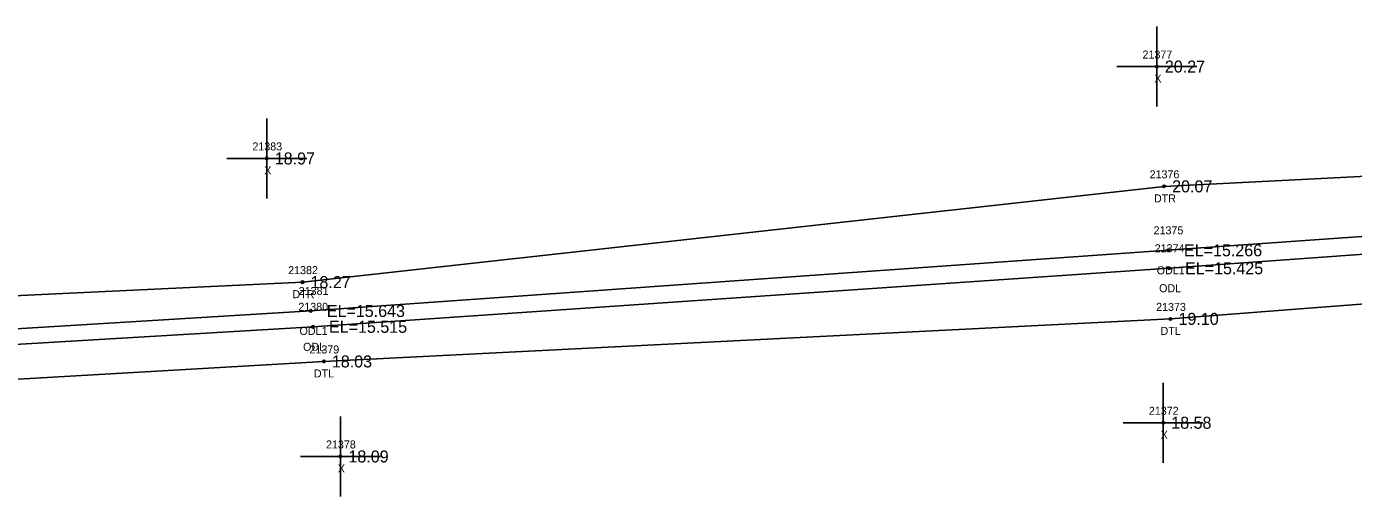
# Model space of a CAD drawing. Extents: x 2655177 to 2656219, y 761780 to 764748.
# Drawn here: x 2655435.9 to 2655601.7, y 763532.7 to 763591.4 of the extents above; entities that cross this region are included whole.
import ezdxf

# ---------------------------------------------------------------- set-up
doc = ezdxf.new("R2010")
doc.units = 0
for name, color, linetype in [('RD_EX_H2O', 7, 'Continuous'), ('RD_EX_H2O_txCode', 7, 'Continuous'), ('RD_EX_Misc', 7, 'Continuous'), ('RD_EX_Misc_txCode', 7, 'Continuous'), ('RD_EX_TX_H2O_ELEV', 7, 'Continuous'), ('RD_EX_TX_Misc_ELEV', 7, 'Continuous'), ('RD_SMD_Locator', 7, 'Continuous')]:
    doc.layers.add(name, color=color, linetype=linetype)

msp = doc.modelspace()

# ---------------------------------------------------------------- linework, layer by layer
at = {"layer": 'RD_EX_H2O'}
for points in [[(2655757.45, 763580.99), (2655680.96, 763576.66), (2655578.06, 763571.44), (2655470.41, 763559.47), (2655370.94, 763554.75), (2655276.75, 763546.33)], [(2655759.35, 763565.01), (2655680.83, 763570.66), (2655578.54, 763563.45), (2655471.45, 763555.87), (2655371.16, 763549.76), (2655277.06, 763543.35)], [(2655759.35, 763565.01), (2655680.78, 763568.55), (2655578.67, 763561.21), (2655471.72, 763553.89), (2655371.24, 763547.95), (2655277.37, 763540.37)], [(2655751.61, 763561.47), (2655681.52, 763562.81), (2655578.85, 763554.88), (2655473.08, 763549.56), (2655371.46, 763543.69), (2655277.89, 763535.39)]]:
    msp.add_lwpolyline(points, dxfattribs=at)
at = {"layer": 'RD_EX_Misc'}
for p, q in [((2655577.15, 763581.41), (2655577.15, 763591.41)), ((2655572.15, 763586.41), (2655582.15, 763586.41)), ((2655465.95, 763569.93), (2655465.95, 763579.93)), ((2655460.95, 763574.93), (2655470.95, 763574.93)), ((2655577.95, 763536.9), (2655577.95, 763546.9)), ((2655475.15, 763532.69), (2655475.15, 763542.69)), ((2655572.95, 763541.9), (2655582.95, 763541.9)), ((2655470.15, 763537.69), (2655480.15, 763537.69))]:
    msp.add_line(p, q, dxfattribs=at)
at = {"layer": 'RD_SMD_Locator'}
for centre in [(2655577.15, 763586.41), (2655465.95, 763574.93), (2655578.06, 763571.44), (2655578.54, 763563.45), (2655578.67, 763561.21), (2655470.41, 763559.47), (2655471.45, 763555.87), (2655578.85, 763554.88), (2655471.72, 763553.89), (2655473.08, 763549.56), (2655577.95, 763541.9), (2655475.15, 763537.69)]:
    msp.add_circle(centre, 0.15, dxfattribs=at)

# ---------------------------------------------------------------- texts
at = {"layer": 'RD_EX_H2O_txCode'}
for s, p in [('21376', (2655576.24, 763572.44)), ('DTR', (2655576.79, 763569.44)), ('21375', (2655576.74, 763565.45)), ('21374', (2655576.88, 763563.21)), ('21382', (2655468.62, 763560.47)), ('ODL1', (2655577.13, 763560.45)), ('ODL', (2655577.43, 763558.21)), ('DTR', (2655469.15, 763557.47)), ('21381', (2655469.94, 763557.87)), ('21380', (2655469.89, 763555.89)), ('21373', (2655577.06, 763555.88)), ('ODL1', (2655470.04, 763552.87)), ('DTL', (2655577.61, 763552.88)), ('ODL', (2655470.48, 763550.89)), ('21379', (2655471.28, 763550.56)), ('DTL', (2655471.83, 763547.56))]:
    msp.add_text(s, height=1, dxfattribs=at).set_placement(p)
at = {"layer": 'RD_EX_Misc_txCode'}
for s, p in [('21377', (2655575.36, 763587.41)), ('X', (2655576.84, 763584.41)), ('21383', (2655464.15, 763575.93)), ('X', (2655465.63, 763572.93)), ('21372', (2655576.15, 763542.9)), ('X', (2655577.63, 763539.9)), ('21378', (2655473.35, 763538.69)), ('X', (2655474.83, 763535.69))]:
    msp.add_text(s, height=1, dxfattribs=at).set_placement(p)
at = {"layer": 'RD_EX_TX_H2O_ELEV'}
for s, p in [('20.07', (2655579.06, 763570.69)), ('EL=15.266', (2655580.54, 763562.7)), ('EL=15.425', (2655580.67, 763560.46)), ('18.27', (2655471.41, 763558.72)), ('EL=15.643', (2655473.45, 763555.12)), ('EL=15.515', (2655473.72, 763553.14)), ('19.10', (2655579.85, 763554.13)), ('18.03', (2655474.08, 763548.81))]:
    msp.add_text(s, height=1.5, dxfattribs=at).set_placement(p)
at = {"layer": 'RD_EX_TX_Misc_ELEV'}
for s, p in [('20.27', (2655578.15, 763585.66)), ('18.97', (2655466.95, 763574.18)), ('18.58', (2655578.95, 763541.15)), ('18.09', (2655476.15, 763536.94))]:
    msp.add_text(s, height=1.5, dxfattribs=at).set_placement(p)

doc.saveas('drawing.dxf')
